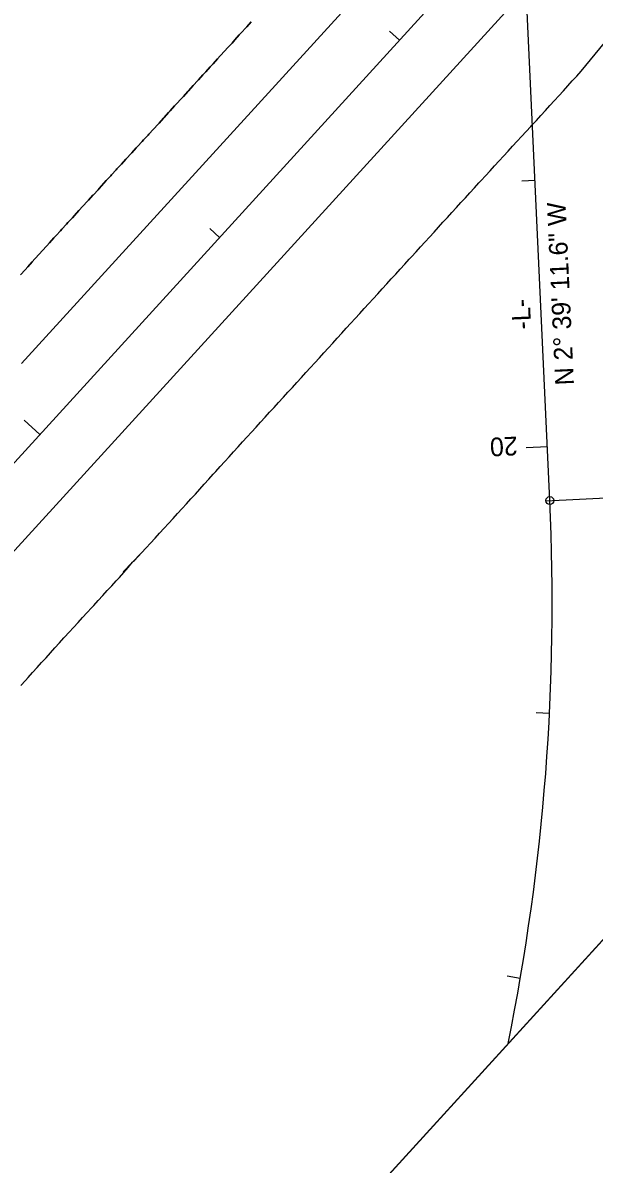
# Model space of a CAD drawing. Extents: x 1807040 to 1808827, y 913493 to 915218.
# Drawn here: x 1807703.5 to 1807917.6, y 914236.2 to 914664.2 of the extents above; entities that cross this region are included whole.
import ezdxf

# ---------------------------------------------------------------- set-up
doc = ezdxf.new("R2010")
doc.units = 0
for name, color, linetype in [('Old_Level_18', 7, 'Continuous'), ('Prop EOT', 7, 'Continuous'), ('Prop Horizontal Alignment Direction Label', 7, 'Continuous'), ('Prop Horizontal Alignment Station Label', 7, 'Continuous'), ('Prop Horizontal Alignment Tick Label', 7, 'Continuous'), ('Prop Horizontal Alignment Tick Large', 7, 'Continuous'), ('Prop Horizontal Alignment Tick Small', 7, 'Continuous'), ('Scratch_Level_0', 7, 'Continuous'), ('Scratch_Level_1', 7, 'Continuous'), ('Scratch_Level_3', 7, 'Continuous')]:
    doc.layers.add(name, color=color, linetype=linetype)

msp = doc.modelspace()

# ---------------------------------------------------------------- linework, layer by layer
at = {"layer": 'Old_Level_18'}
msp.add_line((1808438.77, 914888.63), (1807428.35, 913780.01), dxfattribs=at)
at = {"layer": 'Prop EOT'}
for p, q in [((1807702.96, 914536.44), (1808029.68, 914894.91)), ((1807613.95, 914371.74), (1808063.17, 914864.38))]:
    msp.add_line(p, q, dxfattribs=at)
for points in [[(1807702.61, 914569.75), (1807704.27, 914571.63), (1807705.28, 914572.77), (1807706.97, 914574.62), (1807707.99, 914575.75), (1807709.68, 914577.59), (1807710.75, 914578.75), (1807712.41, 914580.61), (1807713.4, 914581.72), (1807715.09, 914583.57), (1807715.89, 914584.44), (1807717.56, 914586.3), (1807718.1, 914586.9), (1807719.79, 914588.74), (1807720.33, 914589.32), (1807722.03, 914591.16), (1807722.79, 914591.99), (1807724.47, 914593.84), (1807725.99, 914595.53), (1807727.69, 914597.36), (1807728.04, 914597.75), (1807729.75, 914599.58), (1807729.96, 914599.8), (1807731.64, 914601.65), (1807732.04, 914602.1), (1807733, 914603.17), (1807734.74, 914605.06), (1807736.42, 914606.91), (1807736.75, 914607.27), (1807738.44, 914609.11), (1807738.74, 914609.44), (1807740.42, 914611.28), (1807742.1, 914613.13), (1807742.33, 914613.38), (1807744.02, 914615.22), (1807744.3, 914615.52), (1807745.98, 914617.37), (1807746.44, 914617.88), (1807748.13, 914619.72), (1807748.69, 914620.33), (1807750.39, 914622.17), (1807750.7, 914622.51), (1807752.44, 914624.41), (1807754.13, 914626.25), (1807754.51, 914626.67), (1807756.21, 914628.5), (1807756.43, 914628.74), (1807758.1, 914630.6), (1807758.65, 914631.21), (1807760.34, 914633.06), (1807761.1, 914633.9), (1807762.8, 914635.73), (1807763.63, 914636.62), (1807765.31, 914638.47), (1807765.61, 914638.8), (1807767.34, 914640.7), (1807769.01, 914642.56), (1807769.3, 914642.89), (1807770.99, 914644.73), (1807772.04, 914645.88), (1807773.73, 914647.72), (1807774.75, 914648.83), (1807776.41, 914650.69), (1807777.45, 914651.86), (1807779.15, 914653.69), (1807780.19, 914654.81), (1807781.87, 914656.66), (1807782.93, 914657.83), (1807784.6, 914659.69), (1807785.38, 914660.56), (1807787.07, 914662.4), (1807787.37, 914662.72), (1807789.06, 914664.57)], [(1807741.1, 914458.35), (1807747.97, 914465.48), (1807749.66, 914467.33), (1807751.35, 914469.17), (1807753.04, 914471.02), (1807754.72, 914472.86), (1807756.41, 914474.7), (1807758.1, 914476.55), (1807759.79, 914478.39), (1807761.48, 914480.24), (1807763.16, 914482.08), (1807764.77, 914483.84), (1807766.45, 914485.7), (1807768.12, 914487.55), (1807769.8, 914489.41), (1807771.47, 914491.26), (1807773.15, 914493.12), (1807774.82, 914494.98), (1807775.75, 914496), (1807777.43, 914497.85), (1807779.12, 914499.7), (1807780.8, 914501.54), (1807782.48, 914503.39), (1807784.17, 914505.24), (1807785.85, 914507.09), (1807787.53, 914508.94), (1807789.22, 914510.78), (1807790.9, 914512.63), (1807792.58, 914514.48), (1807794.27, 914516.33), (1807795.95, 914518.18), (1807797.63, 914520.02), (1807799.32, 914521.87), (1807801, 914523.72), (1807801.13, 914523.86), (1807802.81, 914525.71), (1807804.5, 914527.55), (1807806.18, 914529.4), (1807807.87, 914531.25), (1807809.55, 914533.09), (1807811.24, 914534.94), (1807812.92, 914536.79), (1807814.61, 914538.64), (1807816.29, 914540.48), (1807817.98, 914542.33), (1807819.66, 914544.18), (1807821.34, 914546.02), (1807823.03, 914547.87), (1807824.71, 914549.72), (1807826.4, 914551.56), (1807828.08, 914553.41), (1807829.77, 914555.26), (1807831.45, 914557.11), (1807833.14, 914558.95), (1807834.82, 914560.8), (1807836.51, 914562.65), (1807838.19, 914564.49), (1807839.88, 914566.34), (1807841.56, 914568.19), (1807843.25, 914570.03), (1807844.93, 914571.88), (1807846.62, 914573.73), (1807848.3, 914575.58), (1807849.16, 914576.52), (1807850.84, 914578.36), (1807852.53, 914580.21), (1807854.21, 914582.06), (1807855.9, 914583.9), (1807857.58, 914585.75), (1807859.27, 914587.6), (1807860.95, 914589.44), (1807862.64, 914591.29), (1807864.32, 914593.14), (1807866.01, 914594.98), (1807867.69, 914596.83), (1807869.38, 914598.68), (1807871.07, 914600.52), (1807872.75, 914602.37), (1807874.44, 914604.22), (1807875.23, 914605.08), (1807876.92, 914606.92), (1807878.61, 914608.76), (1807880.3, 914610.61), (1807881.99, 914612.45), (1807883.68, 914614.29), (1807885.37, 914616.13), (1807887.06, 914617.97), (1807888.75, 914619.81), (1807890.44, 914621.65), (1807892.13, 914623.5), (1807893.82, 914625.34), (1807894.27, 914625.82), (1807895.95, 914627.67), (1807897.64, 914629.52), (1807899.32, 914631.37), (1807901.01, 914633.21), (1807902.69, 914635.06), (1807904.37, 914636.91), (1807906.06, 914638.76), (1807907.74, 914640.6), (1807909.43, 914642.45), (1807911.11, 914644.3), (1807912.79, 914646.15), (1807923.28, 914658.9)], [(1807702.72, 914415.8), (1807704.4, 914417.65), (1807705.42, 914418.76), (1807707.1, 914420.62), (1807708.78, 914422.47), (1807710.46, 914424.32), (1807712.14, 914426.17), (1807713.82, 914428.02), (1807715.5, 914429.87), (1807717.18, 914431.73), (1807718.86, 914433.58), (1807719.1, 914433.84), (1807720.79, 914435.69), (1807722.48, 914437.53), (1807724.16, 914439.38), (1807725.85, 914441.22), (1807727.54, 914443.06), (1807729.23, 914444.91), (1807730.02, 914445.77), (1807731.71, 914447.62), (1807733.39, 914449.46), (1807735.08, 914451.31), (1807736.77, 914453.15), (1807738.45, 914455), (1807739.64, 914456.3), (1807741.29, 914458.17), (1807742.94, 914460.05), (1807744.59, 914461.93), (1807744.95, 914462.35), (1807745.26, 914462.66)]]:
    msp.add_lwpolyline(points, dxfattribs=at)
at = {"layer": 'Prop Horizontal Alignment Station Label'}
msp.add_line((1807899.5, 914485.04), (1808026.15, 914490.91), dxfattribs=at)
msp.add_circle((1807901, 914485.11), 1.5, dxfattribs=at)
at = {"layer": 'Prop Horizontal Alignment Tick Large'}
for p, q in [((1807709.87, 914509.87), (1807703.96, 914515.26)), ((1807900.07, 914505.18), (1807892.08, 914504.81))]:
    msp.add_line(p, q, dxfattribs=at)
at = {"layer": 'Prop Horizontal Alignment Tick Small'}
for p, q in [((1807844.59, 914657.69), (1807840.9, 914661.06)), ((1807895.44, 914605.07), (1807890.45, 914604.84)), ((1807777.23, 914583.78), (1807773.53, 914587.15)), ((1807900.87, 914405.23), (1807895.87, 914405.48)), ((1807889.93, 914305.89), (1807885, 914306.74))]:
    msp.add_line(p, q, dxfattribs=at)
at = {"layer": 'Scratch_Level_0'}
for p, q in [((1807702.96, 914536.44), (1808029.68, 914894.91)), ((1808063.17, 914864.38), (1807658.9, 914421.03))]:
    msp.add_line(p, q, dxfattribs=at)
for points in [[(1807789.06, 914664.57), (1807787.37, 914662.72), (1807787.07, 914662.4), (1807785.38, 914660.56), (1807784.6, 914659.69), (1807782.93, 914657.83), (1807781.87, 914656.66), (1807780.19, 914654.81), (1807779.15, 914653.69), (1807777.45, 914651.86), (1807776.41, 914650.69), (1807774.75, 914648.83), (1807773.73, 914647.72), (1807772.04, 914645.88), (1807770.99, 914644.73), (1807769.3, 914642.89), (1807769.01, 914642.56), (1807767.34, 914640.7), (1807765.61, 914638.8), (1807765.31, 914638.47), (1807763.63, 914636.62), (1807762.8, 914635.73), (1807761.1, 914633.9), (1807760.34, 914633.06), (1807758.65, 914631.21), (1807758.1, 914630.6), (1807756.43, 914628.74), (1807756.21, 914628.5), (1807754.51, 914626.67), (1807754.13, 914626.25), (1807752.44, 914624.41), (1807750.7, 914622.51), (1807750.39, 914622.17), (1807748.69, 914620.33), (1807748.13, 914619.72), (1807746.44, 914617.88), (1807745.98, 914617.37), (1807744.3, 914615.52), (1807744.02, 914615.22), (1807742.33, 914613.38), (1807742.1, 914613.13), (1807740.42, 914611.28), (1807738.74, 914609.44), (1807738.44, 914609.11), (1807736.75, 914607.27), (1807736.42, 914606.91), (1807734.74, 914605.06), (1807733, 914603.17), (1807732.04, 914602.1), (1807731.64, 914601.65), (1807729.96, 914599.8), (1807729.75, 914599.58), (1807728.04, 914597.75), (1807727.69, 914597.36), (1807725.99, 914595.53), (1807724.47, 914593.84), (1807722.79, 914591.99), (1807722.03, 914591.16), (1807720.33, 914589.32), (1807719.79, 914588.74), (1807718.1, 914586.9), (1807717.56, 914586.3), (1807715.89, 914584.44), (1807715.09, 914583.57), (1807713.4, 914581.72), (1807712.41, 914580.61), (1807710.75, 914578.75), (1807709.68, 914577.59), (1807707.99, 914575.75), (1807706.97, 914574.62), (1807705.28, 914572.77), (1807704.27, 914571.63), (1807702.61, 914569.75)], [(1807745.26, 914462.66), (1807747.97, 914465.48), (1807749.66, 914467.33), (1807751.35, 914469.17), (1807753.04, 914471.02), (1807754.72, 914472.86), (1807756.41, 914474.7), (1807758.1, 914476.55), (1807759.79, 914478.39), (1807761.48, 914480.24), (1807763.16, 914482.08), (1807764.77, 914483.84), (1807766.45, 914485.7), (1807768.12, 914487.55), (1807769.8, 914489.41), (1807771.47, 914491.26), (1807773.15, 914493.12), (1807774.82, 914494.98), (1807775.75, 914496), (1807777.43, 914497.85), (1807779.12, 914499.7), (1807780.8, 914501.54), (1807782.48, 914503.39), (1807784.17, 914505.24), (1807785.85, 914507.09), (1807787.53, 914508.94), (1807789.22, 914510.78), (1807790.9, 914512.63), (1807792.58, 914514.48), (1807794.27, 914516.33), (1807795.95, 914518.18), (1807797.63, 914520.02), (1807799.32, 914521.87), (1807801, 914523.72), (1807801.13, 914523.86), (1807802.81, 914525.71), (1807804.5, 914527.55), (1807806.18, 914529.4), (1807807.87, 914531.25), (1807809.55, 914533.09), (1807811.24, 914534.94), (1807812.92, 914536.79), (1807814.61, 914538.64), (1807816.29, 914540.48), (1807817.98, 914542.33), (1807819.66, 914544.18), (1807821.34, 914546.02), (1807823.03, 914547.87), (1807824.71, 914549.72), (1807826.4, 914551.56), (1807828.08, 914553.41), (1807829.77, 914555.26), (1807831.45, 914557.11), (1807833.14, 914558.95), (1807834.82, 914560.8), (1807836.51, 914562.65), (1807838.19, 914564.49), (1807839.88, 914566.34), (1807841.56, 914568.19), (1807843.25, 914570.03), (1807844.93, 914571.88), (1807846.62, 914573.73), (1807848.3, 914575.58), (1807849.16, 914576.52), (1807850.84, 914578.36), (1807852.53, 914580.21), (1807854.21, 914582.06), (1807855.9, 914583.9), (1807857.58, 914585.75), (1807859.27, 914587.6), (1807860.95, 914589.44), (1807862.64, 914591.29), (1807864.32, 914593.14), (1807866.01, 914594.98), (1807867.69, 914596.83), (1807869.38, 914598.68), (1807871.07, 914600.52), (1807872.75, 914602.37), (1807874.44, 914604.22), (1807875.23, 914605.08), (1807876.92, 914606.92), (1807878.61, 914608.76), (1807880.3, 914610.61), (1807881.99, 914612.45), (1807883.68, 914614.29), (1807885.37, 914616.13), (1807887.06, 914617.97), (1807888.75, 914619.81), (1807890.44, 914621.65), (1807892.13, 914623.5), (1807893.82, 914625.34), (1807894.27, 914625.82), (1807895.95, 914627.67), (1807897.64, 914629.52), (1807899.32, 914631.37), (1807901.01, 914633.21), (1807902.69, 914635.06), (1807904.37, 914636.91), (1807906.06, 914638.76), (1807907.74, 914640.6), (1807909.43, 914642.45), (1807911.11, 914644.3), (1807912.79, 914646.15), (1807923.28, 914658.9)], [(1807702.72, 914415.8), (1807704.4, 914417.65), (1807705.42, 914418.76), (1807707.1, 914420.62), (1807708.78, 914422.47), (1807710.46, 914424.32), (1807712.14, 914426.17), (1807713.82, 914428.02), (1807715.5, 914429.87), (1807717.18, 914431.73), (1807718.86, 914433.58), (1807719.1, 914433.84), (1807720.79, 914435.69), (1807722.48, 914437.53), (1807724.16, 914439.38), (1807725.85, 914441.22), (1807727.54, 914443.06), (1807729.23, 914444.91), (1807730.02, 914445.77), (1807731.71, 914447.62), (1807733.39, 914449.46), (1807735.08, 914451.31), (1807736.77, 914453.15), (1807738.45, 914455), (1807739.64, 914456.3), (1807741.29, 914458.17), (1807742.94, 914460.05), (1807744.59, 914461.93), (1807744.95, 914462.35), (1807745.26, 914462.66)]]:
    msp.add_lwpolyline(points, dxfattribs=at)
at = {"layer": 'Scratch_Level_1'}
for points in [[(1807040.33, 914133.66), (1807040.33, 914133.66), (1807428.35, 913780.01), (1808256.27, 914688.39), (1807868.25, 915042.04)], [(1807489.01, 913846.57), (1807877.03, 913492.93), (1808826.79, 914534.98), (1808438.77, 914888.63)]]:
    msp.add_lwpolyline(points, close=True, dxfattribs=at)
at = {"layer": 'Scratch_Level_3'}
for p, q in [((1807238.34, 913992.52), (1808046.68, 914879.41)), ((1807901, 914485.11), (1807884.43, 914842.75))]:
    msp.add_line(p, q, dxfattribs=at)
msp.add_arc((1807068.89, 914446.55), 833, 348.56817, 2.65322, dxfattribs=at)

# ---------------------------------------------------------------- texts
at = {"layer": 'Prop Horizontal Alignment Direction Label'}
for s, p in [('N 2%%d 39\' 11.6" W', (1807910.05, 914528.48)), ('-L-', (1807894.01, 914549.4))]:
    msp.add_text(s, height=7, rotation=92.6532, dxfattribs=at).set_placement(p)
at = {"layer": 'Prop Horizontal Alignment Tick Label'}
msp.add_text('20', height=7, rotation=182.6532, dxfattribs=at).set_placement((1807888.79, 914509.1))

doc.saveas('drawing.dxf')
